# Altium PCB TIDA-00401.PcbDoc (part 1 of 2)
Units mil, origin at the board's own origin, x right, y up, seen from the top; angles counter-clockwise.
Board outline 3543.31 x 2362.2 mil, 2 copper layers (Top Layer, Bottom Layer), stack 62 mil thick; 132 components, 43 nets, 274 pads, 44 vias.
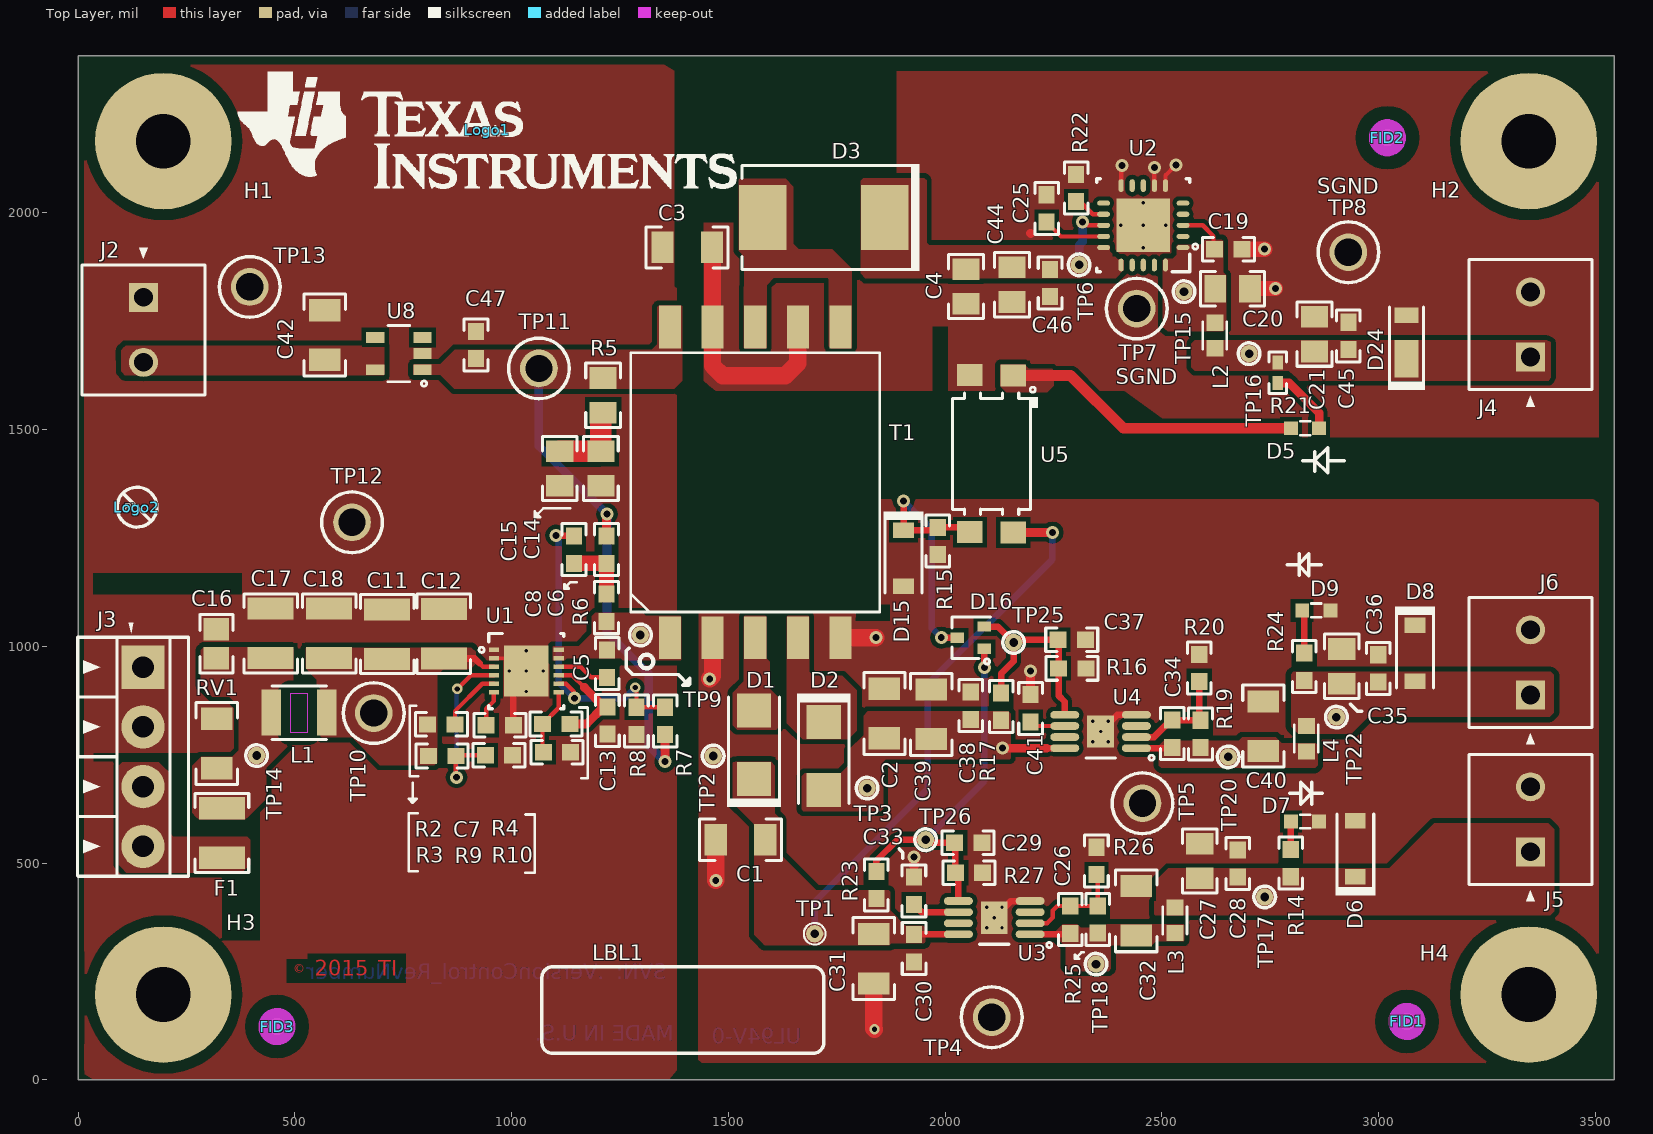
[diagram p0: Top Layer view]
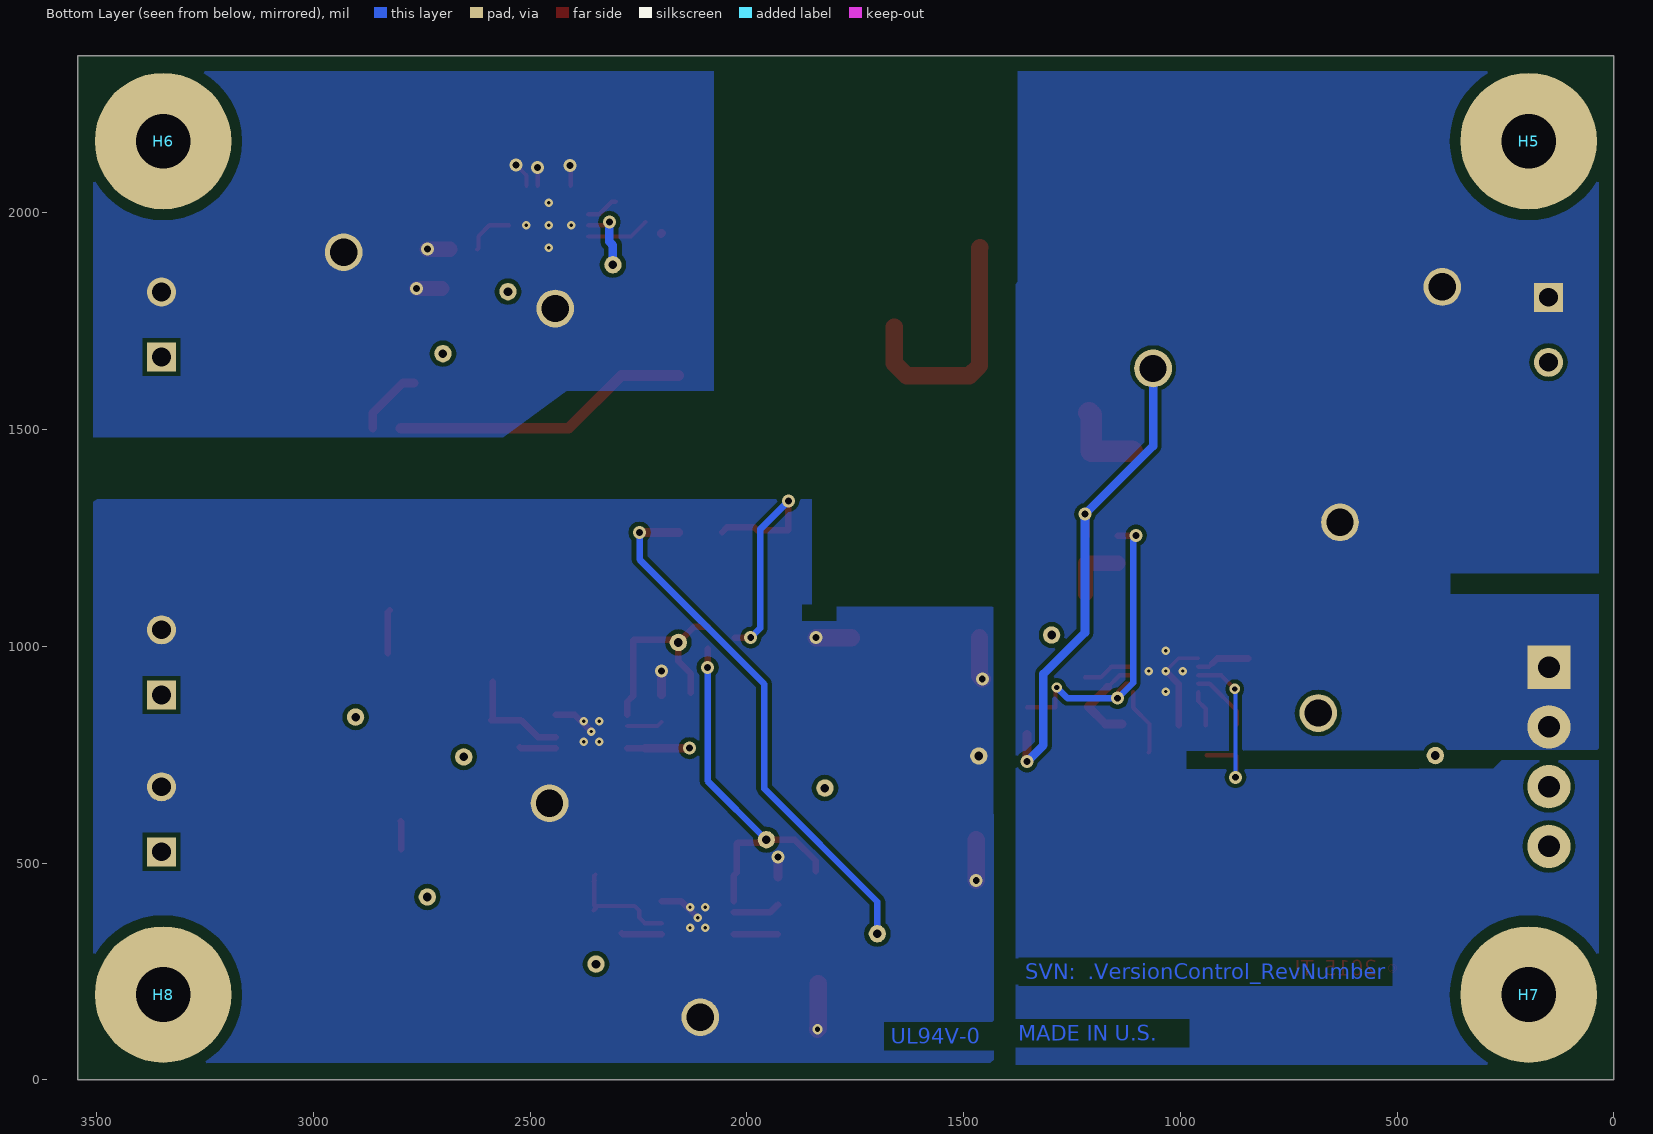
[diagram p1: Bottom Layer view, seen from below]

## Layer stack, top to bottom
Top Layer: signal copper 1.4
Dielectric: core 59.2, FR-4, Dk 4.8
Bottom Layer: signal copper 1.4

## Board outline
0,0 0,2362.2 3543.31,2362.2 3543.31,0

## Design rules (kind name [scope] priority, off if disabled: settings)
AcuteAngle [All] p1: minimum=4.50000000000000E+0001 checktracksonly=FALSE
AssemblyTestPointUsage [All] p1: valid=2
Clearance Clearance_mh [(InComponentClass('Mounting Holes')) vs InPolygon] p1: gap=25
Clearance "Clearance POLYGON TO POLYGON" [InPolygon vs InPolygon] p2: gap=12
Clearance Clearance_BoardEdge [OnCopper and Not InComponentClass('Logo') and not InComponentClass('FiducialMark') and not InRegion(1000,500,4000,800) and Not IsKeepout vs IsKeepOut] p3: gap=30
Clearance Clearance_Poly [InPolygon] p4: gap=10
Clearance "Clearance U3 AND U4" [(InPadClass('u3 and u4'))] p5: gap=7.87
Clearance "Clearance_same net" [IsPad vs IsVia] p6: gap=5
Clearance Clearance_1 [All] p7: gap=9
Clearance Clearance_BoardEdge_MountingHoles [OnCopper and InComponentClass('Mounting Holes') vs IsKeepOut] p8: gap=30
Clearance Clearance_BoardEdge_Poly [OnCopper and InPoly vs IsKeepOut] p9: gap=30
ComponentClearance ComponentClearance_Shunt [InComponentClass('Header') vs InComponentClass('Shunt')] p1 off: gap=0 collisioncheckmode=3 verticalgap=0 showdistances=FALSE
ComponentClearance ComponentClearance_MountingHoles_FiducialMarks [InComponentClass('Mounting Holes') vs InComponentClass('FiducialMark')] p2 off: gap=50 collisioncheckmode=3 verticalgap=10 showdistances=FALSE
ComponentClearance ComponentClearance_Logo [InComponentClass('Logo')] p3 off: gap=50 collisioncheckmode=3 verticalgap=10 showdistances=FALSE
ComponentClearance ComponentClearance_ScrewToNut [(HasFootprint('NY PMS 440 0025 PH')) vs (HasFootprint('Keystone_1902C'))] p4 off: gap=5 collisioncheckmode=3 verticalgap=10 showdistances=FALSE
ComponentClearance ComponentClearance_MountingHoles [InComponentClass('Mounting Holes')] p5 off: gap=50 collisioncheckmode=3 verticalgap=100000 showdistances=FALSE
ComponentClearance ComponentClearance_SmallPassives [HasFootprint('0201*') or HasFootprint('0402*') or HasFootprint('0508') or HasFootprint('0603*') or HasFootprint('0612') or HasFootprint('0805*') or HasFootprint('0815*') or HasFootprint('0830*') or HasFootprint('1206*') or HasFootprint('1210*') or HasFootprint('1808*') or HasFootprint('1812*') or HasFootprint('1825*') or HasFootprint('2010*') or HasFootprint('2220*') or HasFootprint('2225*') or HasFootprint('2512*') or HasFootprint('2728*') or HasFootprint('3518*') vs HasFootprint('0201*') or HasFootprint('0402*') or HasFootprint('0508') or HasFootprint('0603*') or HasFootprint('0612') or HasFootprint('0805*') or HasFootprint('0815*') or HasFootprint('0830*') or HasFootprint('1206*') or HasFootprint('1210*') or HasFootprint('1808*') or HasFootprint('1812*') or HasFootprint('1825*') or HasFootprint('2010*') or HasFootprint('2220*') or HasFootprint('2225*') or HasFootprint('2512*') or HasFootprint('2728*') or HasFootprint('3518*')] p6 off: gap=20 collisioncheckmode=3 verticalgap=10 showdistances=FALSE
ComponentClearance ComponentClearance_THtoSMT [IsThruComponent vs IsSMTComponent] p7 off: gap=35 collisioncheckmode=3 verticalgap=30 showdistances=FALSE
ComponentClearance ComponentClearance_THtoTH [IsThruComponent vs IsThruComponent] p8 off: gap=20 collisioncheckmode=3 verticalgap=5 showdistances=FALSE
ComponentClearance [All] p9 off: gap=20 collisioncheckmode=3 verticalgap=10 showdistances=FALSE
DiffPairsRouting [All] p1: maxlimit=100 minlimit=10 mostfreqgap=10 maxuncoupledlength=1000
FabricationTestPointUsage TestPointUsage [All] p1: valid=2 allowmultiple=FALSE
FabricationTestpoint Testpoint [All] p1: side=3 testpointundercomponent=TRUE minsize=40 maxsize=100 preferedsize=60 minholesize=0 maxholesize=40 preferedholesize=32 testpointgrid=1 allowsidetop=TRUE allowsidebottom=TRUE usegrid=TRUE gridtolerance=0.01
FanoutControl Fanout_LCC [IsLCC] p1: bgadir=Out bgaviamode=Centered fanoutstyle=Auto fanoutdirection=Alternating viagrid=1 // Fanout_LCC (Default Rule)
FanoutControl Fanout_BGA [IsBGA] p2: bgadir=Out bgaviamode=Centered fanoutstyle=Auto fanoutdirection=Alternating viagrid=1 // Fanout_BGA (Default Rule)
FanoutControl Fanout_Default [All] p4: bgadir=Out bgaviamode=Centered fanoutstyle=Auto fanoutdirection=Alternating viagrid=1 // Fanout_Default (Default Rule)
FanoutControl Fanout_Small [(CompPinCount < 5)] p5: bgadir=Out bgaviamode=Centered fanoutstyle=Auto fanoutdirection=OutThenIn viagrid=1 // Fanout_Small (Default Rule)
HoleSize [All] p1: absolutevalues=TRUE maxlimit=500 minlimit=7.8 maxpercent=80.000 minpercent=20.000
MinimumAnnularRing MinimumAnnularRing_ThermalPadVias [IsVia and InAnyComponent] p1: minimumring=5
MinimumAnnularRing [All] p2: minimumring=5
MinimumSolderMaskSliver MinimumSolderMaskSliver_Logo [InComponentClass('Logo') vs InComponentClass('Logo')] p1: minsoldermaskwidth=0.7
MinimumSolderMaskSliver [All] p2: minsoldermaskwidth=3.94
PlaneConnect [All] p1: planeconnectstyle=Direct reliefexpansion=10 reliefentries=4 reliefconductorwidth=10 reliefairgap=10
PolygonConnect [All] p1: connectstyle=Direct reliefconductorwidth=10 reliefentries=4 polygonreliefangle="90 Angle"
RoutingVias [All] p1: holewidth=10 width=20 viastyle="Through Hole" minholewidth=12 minwidth=24 maxholewidth=16 maxwidth=30
RoutingVias RoutingVias_1 [All] p2: holewidth=12 width=24 viastyle="Through Hole" minholewidth=7.87 minwidth=19.68 maxholewidth=16 maxwidth=30
RoutingVias ThermalPadVias [IsVia and InAnyComponent] p3: holewidth=7.87 width=19.68 viastyle="Through Hole" minholewidth=10 minwidth=20 maxholewidth=12.99 maxwidth=23.62
SMDToCorner [All] p1 off: distance=30000
SilkToSilkClearance SilkToSilkClearance_Pb-FreeLogo [(HasFootprint('Pb-Free_Overlay_Medium') OR HasFootprint('Pb-Free_Overlay_Small')) vs (HasFootprint('Pb-Free_Overlay_Medium') OR HasFootprint('Pb-Free_Overlay_Small'))] p1: silktosilkclearance=0
SilkToSilkClearance [All] p2: silktosilkclearance=5
SilkscreenOverComponentPads [IsPad] p1: minsilkscreentomaskgap=5
SolderMaskExpansion [All] p1: expansion=2.5
Width [All] p1: maxlimit=100 minlimit=6 preferedwidth=10 checkconnectedcopper=TRUE
14 further rules are at their usual default settings.

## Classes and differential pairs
component class TIDA-00401_LDO_1: C19 C20 C21 C25 C26 C27 C28 C29 C30 C31 C32 C33 C34 C35 C36 C37 C38 C39 C40 C41 C44 C45 C46 D5 D6 D7 D8 D9 D15 D16 D24 J4 J5 J6 L2 L3 L4 R14 R15 R16 R17 R19 R20 R21 R22 R23 R24 R25 R26 R27 TP15 TP16 TP17 TP18 TP20 TP22 TP25 TP26 U2 U3 U4 U5
component class "Mounting Holes": H1 H2 H3 H4
component class Logo: Logo1
component class TIDA-00401_HW_1: FID1 FID2 FID3 H1 H2 H3 H4 H5 H6 H7 H8 LBL1 Logo1 Logo2 ZZ1 ZZ2 ZZ3 ZZ4
component class FiducialMark: FID1 FID2 FID3
component class AssemblyNote: ZZ1 ZZ2 ZZ3 ZZ4
component class Label: LBL1
component class TIDA-00401_1: C1 C2 C3 C4 C5 C6 C7 C8 C11 C12 C13 C14 C15 C16 C17 C18 C42 C47 D1 D2 D3 F1 J2 J3 L1 R2 R3 R4 R5 R6 R7 R8 R9 R10 RV1 T1 TP1 TP2 TP3 TP4 TP5 TP6 TP7 TP8 TP9 TP10 TP11 TP12 TP13 TP14 U1 U8
pad class "u3 and u4": U3-1 U3-2 U3-3 U3-4 U3-5 U3-6 U3-7 U3-8 U3-9 U4-1 U4-2 U4-3 U4-4 U4-5 U4-6 U4-7 U4-8 U4-9

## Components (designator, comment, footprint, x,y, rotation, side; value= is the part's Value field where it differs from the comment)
C1 "GRM31CR71H475KA12L" 1206 1528,554 r0 top
C2 "GRM31CR71H475KA12L" 1206 1860,845 r270 top
C3 "VJ1206A102JXGAT5Z" 1206 1405,1920 r180 top
C4 "EMK212BJ106KG-T" 0805_HV 2048,1830 r270 top
C5 "C0603C104J3RAC" 0603#1 1220.2,959.91 r270 top
C6 "C0603C222K5RAC" 0603#1 1219,1223 r90 top
C7 "GRM188R71C223KA01D" 0603#1 972.8,817.84 r0 top
C8 "C0603C104J3RAC" 0603#1 1144,1223 r90 top
C11 "GRM32ER71H106KA12L" 1210 713,1028 r90 top
C12 "GRM32ER71H106KA12L" 1210 844,1029 r90 top
C13 "GRM188R71E105KA12D" 0603#1 1221,829 r270 top
C14 "EMK212BJ106KG-T" 0805_HV 1206,1410 r270 top
C15 "EMK212BJ106KG-T" 0805_HV 1111,1410 r270 top
C16 "C0805C104K1RACTU" 0805 319,1006 r90 top
C17 "GRM32ER71H106KA12L" 1210 444,1030 r90 top
C18 "GRM32ER71H106KA12L" 1210 579,1030 r90 top
C19 "06035C104KAT2A" 0603#1 2653,1916 r180 top
C20 "GRM21BR61C226ME44" 0805_HV 2663,1825 r0 top
C21 "C2012X5R1H475K125AB" 0805_HV 2852,1720 r90 top
C25 "C1608X7R1E105K080AB" 0603#1 2234,2010 r90 top
C26 "06031C103JAT2A" 0603#1 2288.32,369.52 r90 top
C27 "C2012X5R1H475K125AB" 0805_HV 2587,505 r270 top
C28 "06035C104KAT2A" 0603#1 2675,499 r270 top
C29 "06031C103JAT2A" 0603#1 2053,547 r0 top
C30 "06035C104KAT2A" 0603#1 1928.32,303.52 r90 top
C31 "GRM31CR71H475KA12L" 1206 1835.32,279.52 r270 top
C32 "GRM31CR71E106KA12L" 1206 2441,390 r90 top
C33 "06031C103JAT2A" 0603#1 1928,436 r90 top
C34 "06031C103JAT2A" 0603#1 2523.54,798.49 r90 top
C35 "C2012X5R1H475K125AB" 0805_HV 2915,954 r270 top
C36 "06035C104KAT2A" 0603#1 2999,949 r270 top
C37 "06031C103JAT2A" 0603#1 2292,1015 r0 top
C38 "06035C104KAT2A" 0603#1 2059,863 r270 top
C39 "GRM31CR71H475KA12L" 1206 1968,843 r90 top
C40 "GRM31CR71E106KA12L" 1206 2734,816 r90 top
C41 "06031C103JAT2A" 0603#1 2197,857 r90 top
C42 "GRM31CR71H475KA12L" 1206 569,1718 r270 top
C44 "GRM21BR61C226ME44" 0805_HV 2154,1834 r270 top
C45 "06035C104KAT2A" 0603#1 2930,1716 r270 top
C46 "06035C104KAT2A" 0603#1 2242,1838 r90 top
C47 "EMK107B7105KA-T" 0603#1 918,1695 r90 top
D1 "B160-13-F" SMA 1559,773 r90 top
D2 "B160-13-F" SMA 1720,747 r270 top
D3 "B350-13-F" SMC 1720,1989 r180 top
D5 "LED_LG L29K-G2J1-24-Z" LED0603AA 2830,1503 r0 top
D6 "DZ2W18000L" SOD-123 2946,533 r90 top
D7 "LED_LG L29K-G2J1-24-Z" LED0603AA 2830,596 r180 top
D8 "DZ2W18000L" SOD-123 3084,984 r270 top
D9 "LED_LG L29K-G2J1-24-Z" LED0603AA 2856,1083 r0 top
D15 "BZT52C5V1-G3-08" SOD-123 1904,1203 r270 top
D16 "BAT54AWT-TP" SOT-323 2059,1020 r180 top
D24 "PTZTE255.6B" powerDI123 3064,1713 r90 top
F1 "0ZCB0020FF2E" 1210 332,569.24 r270 top
FID1 "Fiducial" Fiducial10-20 3065,134.85 r0 top
FID2 "Fiducial" Fiducial10-20 3020,2173 r0 top
FID3 "Fiducial" Fiducial10-20 459,123 r0 top
H1 "NY PMS 440 0025 PH" "NY PMS 440 0025 PH" 196.85,2165.35 r0 top locked
H2 "NY PMS 440 0025 PH" "NY PMS 440 0025 PH" 3346.46,2165.35 r0 top
H3 "NY PMS 440 0025 PH" "NY PMS 440 0025 PH" 196.85,196.85 r0 top locked
H4 "NY PMS 440 0025 PH" "NY PMS 440 0025 PH" 3346.46,196.85 r0 top locked
H5 "1902C" Keystone_1902C 196.85,2165.35 r180 bottom locked
H6 "1902C" Keystone_1902C 3346.46,2165.35 r180 bottom
H7 "1902C" Keystone_1902C 196.85,196.85 r180 bottom locked
H8 "1902C" Keystone_1902C 3346.46,196.85 r180 bottom locked
J2 "Vout Primary" PhoenixConact_1727010 151,1730 r270 top
J3 "ED555/4DS" TERM_BLK_ED555-4DS 150,952 r270 top
J4 "+5V" PhoenixConact_1727010 3350,1742 r90 top
J5 "+15V" PhoenixConact_1727010 3350,601 r90 top
J6 "-15V" PhoenixConact_1727010 3350,963 r90 top
L1 "3.3µH" IND_B82422H 510,847 r0 top
L2 "1000 OHM" FB0603 2622,1717 r270 top
L3 "1000 OHM" FB0603 2530,368 r90 top
L4 "1000 OHM" FB0603 2833,787 r90 top
LBL1 "Size: 0.65\" x 0.20 \"" Label_650x200 1395,161 r180 top
Logo1 "Texas Instruments" TI_Stacked_Overlay_Medium 944,2191 r0 top
Logo2 "Pb-Free Symbol" Pb-Free_Overlay_Small 136,1321 r0 top
R2 "CRCW0603487KFKEA" 0603#1 838,820 r180 top
R3 "CRCW0603100KFKEA" 0603#1 840,747 r180 top
R4 "CRCW06030000Z0EA" 0603#1 1102.8,820.84 r180 top
R5 "CRCW08050000Z0EA" 0805_HV 1211,1579 r90 top
R6 "CRCW0603100KFKEA" 0603#1 1219,1089 r90 top
R7 "CRCW060310K0FKEA" 0603#1 1354,828 r270 top
R8 "CRCW06031K82FKEA" 0603#1 1288,828 r90 top
R9 "CRCW060318K2FKEA" 0603#2 971,749 r180 top
R10 "CRCW06030000Z0EA" 0603#1 1104.8,755.84 r180 top
R14 "CRCW06034K70JNEA" 0603#1 2797,500 r90 top
R15 "CRCW06034K70JNEA" 0603#1 1983,1243 r270 top
R16 "CRCW06032K20JNEA" 0603#1 2293,949 r180 top
R17 "CRCW06030000Z0EA" 0603#1 2129,861 r270 top
R19 "CRCW0402110KFKED" 0603#1 2589,798 r90 top
R20 "TNPW04029K42BEED" 0603#1 2586,950 r90 top
R21 "CRCW04021K20JNED" 0402 2767,1631 r270 top
R22 "CRCW06030000Z0EA" 0603#1 2302,2057 r90 top
R23 "CRCW06030000Z0EA" 0603#1 1841.32,449.52 r270 top
R24 "CRCW06034K70JNEA" 0603#1 2828,953 r90 top
R25 "CRCW0402110KFKED" 0603#1 2352,370 r90 top
R26 "TNPW04029K42BEED" 0603#1 2349,505 r90 top
R27 "CRCW06032K20JNEA" 0603#1 2055,478 r180 top
RV1 "VC080530A650DP" 1206 320,776 r270 top
T1 "750342706" TR_750342706 1365,1020 r90 top
TP1 "TP1_PD40_D0.5_S50" TP1_PD40_D0.5_S50 1699,337 r90 top
TP2 "TP1_PD40_D0.5_S50" TP1_PD40_D0.5_S50 1465,747 r0 top
TP3 "TP1_PD40_D0.5_S50" TP1_PD40_D0.5_S50 1820,673 r0 top
TP4 "15GND" Keystone5011 2107.32,144.52 r0 top
TP5 "15GND" Keystone5011 2455,638 r0 top
TP6 "TP1_PD40_D0.5_S50" TP1_PD40_D0.5_S50 2309,1880 r0 top
TP7 "SGND" Keystone5011 2442,1779 r0 top
TP8 "SGND" Keystone5011 2930,1909 r0 top
TP9 "TP1_PD40_D0.5_S50" TP1_PD40_D0.5_S50 1297,1026 r0 top
TP10 "+Vin" Keystone5010 682,846 r0 top
TP11 "9V_Non_ISO" Keystone5011 1063,1641 r0 top
TP12 "GNDin" Keystone5011 632,1286 r0 top
TP13 "PGND" Keystone5127 396,1829 r0 top
TP14 "TP1_PD40_D0.5_S50" TP1_PD40_D0.5_S50 412,748 r90 top
TP15 "TP1_PD40_D0.5_S50" TP1_PD40_D0.5_S50 2551,1818 r90 top
TP16 "TP-038" TP1_PD40_D0.5_S50 2701,1675 r90 top
TP17 "TP-038" TP1_PD40_D0.5_S50 2737,422 r90 top
TP18 "TP1_PD40_D0.5_S50" TP1_PD40_D0.5_S50 2348,267 r90 top
TP20 "TP1_PD40_D0.5_S50" TP1_PD40_D0.5_S50 2653,745 r90 top
TP22 "TP-038" TP1_PD40_D0.5_S50 2902.33,836.72 r90 top
TP25 "TP1_PD40_D0.5_S50" TP1_PD40_D0.5_S50 2158,1009 r90 top
TP26 "TP1_PD40_D0.5_S50" TP1_PD40_D0.5_S50 1955,554 r90 top
U1 "LM5160DNT" DNT0012B 1034,943 r0 top
U2 "TPS7A4700RGW" RGW0020A 2457,1971 r180 top
U3 "TPS7A4901DGNR" DGN0008D_N 2113.32,374.2 r180 top
U4 "TPS7A3001DGNR" DGN0008D_N 2358.54,803.49 r180 top
U5 "FOD817DS" N04C 2107,1444 r270 top
U8 "TPS709XXDBV" DBV-5 740,1675 r180 top
ZZ1 "This Assembly Note is for PCB labels only" AssemblyNoteLabel 311,2930 r0 top
ZZ2 "These assemblies are ESD sensitive, ESD precautions shall be observed." AssemblyNote 310,2859.11 r0 top
ZZ3 "These assemblies must be clean and free from flux and all contaminants. Use of no clean flux is not acceptable." AssemblyNote 310,2785.56 r0 top
ZZ4 "These assemblies must comply with workmanship standards IPC-A-610 Class 2, unless otherwise specified." AssemblyNote 312,2705 r0 top

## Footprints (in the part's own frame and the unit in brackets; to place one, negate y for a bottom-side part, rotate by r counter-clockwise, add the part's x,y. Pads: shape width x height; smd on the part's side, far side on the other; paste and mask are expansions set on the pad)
0402 [mm] "0402 from SM-752 data"
  rect 0.8x0.6 smd: 1(-0.6,0) 2(0.6,0)
  silkscreen extent -1.22,-0.52 1.22,0.52, body extent -0.55,-0.3 0.55,0.3, height 0.6
0603#1 [mm] "0603 from SM-752 data"
  rect 1x0.95 smd: 1(-0.8,0) 2(0.8,0)
  silkscreen extent -1.52,-0.69 1.52,0.69, body extent -0.87,-0.47 0.87,0.47, height 0.85
0603#2 [mm] "0603 from SM-752 data"
  rect 1x0.95 smd: 1(-0.8,0)
  rect 1x0.95 smd mask+0.064: 2(0.8,0)
  silkscreen extent -1.52,-0.69 1.52,0.69, body extent -0.87,-0.47 0.87,0.47, height 0.85
0805 [mm] "0805 from SM-752 data"
  rect 1.3x1.5 smd: 1(-0.85,0) 2(0.85,0)
  silkscreen extent -1.72,-0.97 1.72,0.97, body extent -1.1,-0.72 1.1,0.72, height 1.1
0805_HV [mil] "0805 with 30mil clearance between pads"
  rect 50x63 smd: 1(-40,0) 2(40,0)
  silkscreen extent -74,-40 74,40, body extent -43,-29 43,29, height 43
1206 [mm] "1206 from SM-752 data"
  rect 1.3x1.85 smd: 1(-1.45,0) 2(1.45,0)
  silkscreen extent -2.4,-1.21 2.4,1.21, body extent -1.7,-0.9 1.7,0.9, height 1.35
1210 [mm] "1210 from SM-752 data"
  rect 1.3x2.7 smd: 1(-1.45,0) 2(1.45,0)
  silkscreen extent -2.32,-1.57 2.32,1.57, body extent -1.7,-1.35 1.7,1.35, height 1.35
AssemblyNote [mil] "Assembly Note"
AssemblyNoteLabel [mil] "Assembly Note for PCB Labels"
DBV-5 [mil]
  rect 42x25 smd: 1(-54.5,37) 2(-54.5,0) 3(-54.5,-37) 4(54.5,-37) 5(54.5,37)
  silkscreen extent -64,-65 25,75
DGN0008D_N [mm] "TSOP, 8-Leads, Body 3x3mm, Pitch 0.65mm, Thermal Pad 1.89x1.57mm, IPC Medium Density"
  oval 1.7x0.45 smd mask+0.048: 1(-2.1,0.975) 2(-2.1,0.325) 3(-2.1,-0.325) 4(-2.1,-0.975) 5(2.1,-0.975) 6(2.1,-0.325) 7(2.1,0.325) 8(2.1,0.975)
  rect 1.57x1.89 smd mask+0.076: 9(0,0)
  silkscreen extent -0.85,1.55 0.85,1.55, body extent -2.45,-1.5 2.45,1.5, height 0.94
DNT0012B [mm] "SON, 12-Leads, Body 4x4mm, Pitch 0.5mm"
  rect 0.6x0.25 smd: 1(-1.9,1.25) 2(-1.9,0.75) 3(-1.9,0.25) 4(-1.9,-0.25) 5(-1.9,-0.75) 6(-1.9,-1.25) 7(1.9,-1.25) 8(1.9,-0.75) 9(1.9,-0.25) 10(1.9,0.25) 11(1.9,0.75) 12(1.9,1.25)
  rect 2.6x3 smd paste-1.3: 13(0,0)
  silkscreen extent -2.2,-2.2 2.2,2.2, body extent -2.05,-2.05 2.05,2.05, height 0.81
FB0603 [mm]
  rect 0.95x1 smd: 1(-0.75,0) 2(0.75,0)
  silkscreen extent -0.8,-0.7 0.8,0.7
Fiducial10-20 [mm]
  round 1 smd mask+0.5: 1(0,0)
  Top Layer keep-out circle w1.178: c0,0 r0.5
IND_B82422H [mm]
  rect 1.15x2.7 smd: 1(-1.625,0) 2(1.625,0)
  Top Layer keep-out region: -0.507,-1.147 0.509,-1.147 0.509,1.119 -0.507,1.119
  silkscreen extent -1.6,-1.57 1.6,1.57, body extent -1.6,-1.25 1.6,1.25, height 2.4
Keystone5010 [mil] "Keystone Multipurpose loops"
  round 87 hole 63: 1(0,0)
  silkscreen extent -70,-70 70,70, body extent -63,-63 63,62, height 319
Keystone5011 [mil] "Keystone Multipurpose loops"
  round 87 hole 63: 1(0,0)
  silkscreen extent -70,-70 70,70, body extent -63,-63 63,62, height 319
Keystone5127 [mil] "Keystone Multipurpose loops"
  round 87 hole 63: 1(0,0)
  silkscreen extent -70,-70 70,70, body extent -63,-63 63,62, height 319
Keystone_1902C [mil] "Hex Standoff, 4-40 threaded, nylon"
  body extent -145,-126 146,126, height 501
Label_650x200 [mil] "Thermal Transfer Label"
  round 1 on Mech13: 0(0,0)
  silkscreen extent -325,-100 325,100, body extent -326,-101 326,101, height 1
LED0603AA [mil]
  rect 32x32 smd: 1(-32.48,0) 2(32.48,0)
  silkscreen extent -11,-16 11,16
N04C [mm] "FAIRCHILD"
  rect 1.3x1.5 smd mask+0.065: 1(-4.587,1.27) 2(-4.612,-1.27) 3(4.588,-1.27) 4(4.613,1.27)
  silkscreen extent -3.91,-2.3 3.56,2.72, body extent -5.08,-2.3 5.08,2.3, height 3.87
"NY PMS 440 0025 PH" [mm] "4-40 nylon screw and mounting hole"
  round 8 hole 3.2: 1(0,0)
  body extent -3.3,-3.3 3.3,3.3, height 2.69
Pb-Free_Overlay_Small [mil]
  silkscreen extent -46,-46 46,46
PhoenixConact_1727010 [mm]
  rect 1.7x1.7 hole 1.1: 1(-1.905,0)
  round 1.7 hole 1.1: 2(1.905,0)
  silkscreen extent -4.8,-3.6 3.81,3.6, body extent -3.81,-3.6 3.81,3.7, height 8.52
powerDI123 [mm] "Diodes Inc recommended land pattern, document number DS30628 Rev. 6-2"
  rect 2.2x1.4 smd: 1(-1.275,0)
  rect 0.9x1.4 smd: 2(1.275,0)
  silkscreen extent -3.1,-1.09 1.76,1.09, body extent -2.38,-0.97 1.52,0.96, height 1
RGW0020A [mm] "QFN, 20-Leads, Body 5x5mm, Pitch 0.65mm, Thermal Pad 3.15x3.15mm, TI Recommended"
  oval 0.75x0.3 smd: 1(-2.325,1.3) 2(-2.325,0.65) 3(-2.325,0) 4(-2.325,-0.65) 5(-2.325,-1.3) 11(2.325,-1.3) 12(2.325,-0.65) 13(2.325,0) 14(2.325,0.65) 15(2.325,1.3)
  oval 0.3x0.75 smd: 6(-1.3,-2.325) 7(-0.65,-2.325) 8(0,-2.325) 9(0.65,-2.325) 10(1.3,-2.325) 16(1.3,2.325) 17(0.65,2.325) 18(0,2.325) 19(-0.65,2.325) 20(-1.3,2.325)
  rect 3.15x3.15 smd paste-1.575: 21(0,0)
  silkscreen extent -2.73,-2.73 2.73,2.73, body extent -2.58,-2.57 2.57,2.58, height 1.01
SMA [mm] "Molded Diode, 2-Leads, Body 4.3x2.6mm, IPC Medium Density, based on OnSemi component dimensions and land pattern"
  rect 2x2 smd: 1(-2,0) 2(2,0)
  silkscreen extent -3.66,-1.57 2.79,1.57, body extent -2.6,-1.3 2.6,1.3, height 2.42
SMC [mil] "Molded Diode, 2-Leads, Body 6.9x5.8mm, IPC Medium Density, based on OnSemi component dimensions and land patterns"
  rect 110x150 smd: 1(-140.49,0) 2(140.49,0)
  silkscreen extent -221,-124 189,123, body extent -156,-116 156,116, height 91
SOD-123 [mm] "On Semi recommended land pattern"
  rect 0.915x1.22 smd: 1(-1.637,0) 2(1.637,0)
  silkscreen extent -2.74,-1.17 2.03,1.17, body extent -1.93,-0.9 1.93,0.9, height 1.35
SOT-323 [mm] "Zetex recommended land pattern.  March 2007"
  rect 0.8x0.6 smd: 1(-0.8,0.65) 2(-0.8,-0.65) 3(0.8,0)
  silkscreen extent -1.14,-1.22 1.09,1.55, body extent -1.13,-1.13 1.12,1.12, height 1.13
TERM_BLK_ED555-4DS [mm]
  rect 2.54x2.54 hole 1.27: 1(0,0)
  round 2.54 hole 1.27: 2(3.5,0) 3(7,0) 4(10.5,0)
  silkscreen extent -2.59,-3.83 12.25,2.67, body extent -1.75,-3.8 12.25,2.7, height 8.2
TI_Stacked_Overlay_Medium [mil]
  silkscreen extent -576,-136 576,134
TP1_PD40_D0.5_S50 [mil]
  round 40 hole 20: 1(0,0)
  silkscreen extent -25,-25 25,25
TR_750342706 [mm] "Transformer WE_750342706"
  rect 2.5x1.3 smd: 1(0,0) 2(0,-2.5) 3(0,-5) 4(0,-7.5) 5(0,-10) 6(18.2,-10) 7(18.2,-7.5) 8(18.2,-5) 9(18.2,-2.5) 10(18.2,0)
  silkscreen extent -1.8,-12.3 16.7,2.3, body extent -0.9,-12.3 19.1,2.3, height 8.25

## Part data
C1 C2 C31 C39 C42: "CAP, CERM, 4.7uF, 50V, +/-10%, X7R, 1206"
C3: "CAP, CERM, 1000pF, 1000V, +/-5%, C0G/NP0, 1206"
C4 C14 C15: "CAP, CERM, 10uF, 16V, +/-10%, X5R, 0805"
C5 C8: "CAP, CERM, 0.1uF, 25V, +/-5%, X7R, 0603"
C6: "CAP, CERM, 2200pF, 50V, +/-10%, X7R, 0603"
C7: "CAP, CERM, 0.022uF, 16V, +/-10%, X7R, 0603"
C11 C12 C17 C18: "CAP, CERM, 10uF, 50V, +/-10%, X7R, 1210"
C13 C25: "CAP, CERM, 1uF, 25V, +/-10%, X7R, 0603"
C16: "CAP, CERM, 0.1uF, 100V, +/-10%, X7R, 0805"
C19 C28 C30 C36 C38 C45 C46: "CAP, CERM, 0.1uF, 50V, +/-10%, X7R, 0603"
C20 C44: "CAP, CERM, 22uF, 16V, +/-20%, X5R, 0805"
C21 C27 C35: "CAP, CERM, 4.7uF, 50V, +/-10%, X5R, 0805"
C26 C29 C33 C34 C37 C41: "CAP, CERM, 0.01uF, 100V, +/-5%, X7R, 0603"
C32 C40: "CAP, CERM, 10uF, 25V, +/-10%, X7R, 1206"
C47: "CAP, CERM, 1 µF, 16 V, +/- 10%, X7R, 0603"
D1 D2: "Diode, Schottky, 60 V, 1 A, SMA"
D3: "Diode, Schottky, 50 V, 3 A, SMC"
D5 D7 D9: "LED SmartLED Green 570NM"
D6 D8: "Diode, Zener, 18V, 1W, SOD-123"
D15: "Diode, Zener, 5.1 V, 500 mW, SOD-123"
D16: "Diode, Schottky, 30 V, 0.2 A, SOT-323"
D24: "DIODE ZENER 5.9V 1W PMDS"
F1: library part 37215000001, "PTC RESTTBLE 0.05A 60V CHIP 1210"
FID1 FID2 FID3: "Fiducial mark.  There is nothing to buy or mount."
H1 H2 H3 H4: "Machine Screw, Round, #4-40 x 1/4, Nylon, Philips panhead"
H5 H6 H7 H8: "Standoff, Hex, 0.5\"L #4-40 Nylon"
J2 J4 J5 J6: library part 1727010, "Conn Term Block, 2POS, 3.81mm, TH"
J3: "Terminal Block, 6A, 3.5mm Pitch, 4-Pos, TH"
L1: library part IND_ELJEA_SERIES, "Inductor, Chip, ±10%"
L2: library part MMZ1608B102C, "FERRITE CHIP 1000 OHM 1500MA 0805"
L3 L4: library part MMZ1608B102C, "FERRITE CHIP 1000 OHM 300MA 0603"
LBL1: library part THT-14-423-10, "Thermal Transfer Printable Labels, 0.650\" W x 0.200\" H - 10,000 per roll"
Logo1: library part TI_Logo, "Texas Instrument Corporate Signature"
Logo2: library part Pb-Free
R2: "RES, 487k ohm, 1%, 0.1W, 0603"
R3: "RES, 100 k, 1%, 0.1 W, 0603"
R4 R10 R17 R22 R23: "RES, 0, 5%, 0.1 W, 0603"
R5: "RES, 0, 5%, 0.125 W, 0805"
R6: "RES, 100k ohm, 1%, 0.1W, 0603"
R7: "RES, 10.0k ohm, 1%, 0.1W, 0603"
R8: "RES, 1.82 k, 1%, 0.1 W, 0603"
R9: "RES, 18.2k ohm, 1%, 0.1W, 0603"
R14 R15 R24: "RES, 4.7k ohm, 5%, 0.1W, 0603"
R16 R27: "RES, 2.2 k, 5%, 0.1 W, 0603"
R19 R25: "RES, 110k ohm, 1%, 0.063W, 0402"
R20 R26: library part CRCW04029K31FKED, "RES, 9.42k ohm, 1%, 0.063W, 0402"
R21: "RES, 1.2k ohm, 5%, 0.063W, 0402"
RV1: library part VC120648D101DP, "VARISTOR 36.9V 30A 0805"
T1: library part 750342178, "Transformer, 50 uH, SMT"
TP1 TP2 TP3 TP6 TP9 TP14 TP15 TP18 TP20 TP25 TP26: library part TP-040_RND, "Test Point 40mil pad 20mil drill"
TP4 TP5 TP7 TP8 TP11 TP12: library part 5011, "Test Point, Multipurpose, Black, TH"
TP10: library part 5010, "Test Point, Multipurpose, Red, TH"
TP13: library part 5127, "Test Point, Multipurpose, Blue, TH"
TP16 TP17 TP22: "Test Point 40mil pad 20mil drill"
U1: "Wide Input 65V, 1.5A Synchronous Step-Down DC-DC Converter, DNT0012B"
U2: "36-V, 1-A, 4.17-µVRMS, RF LDO Voltage Regulator, RGW0020A"
U3: "Single Output High PSRR LDO, 150 mA, Adjustable 1.2 to 33 V Output, 3 to 36 V Input, with Ultra-Low Noise, 8-pin MSOP (DGN), -40 to 125 degC, Green (RoHS & no Sb/Br)"
U4: "Single Output High PSRR LDO, 200 mA, Adjustable -1.18 to -33 V Output, -3 to -36 V Input, with Ultra-Low Noise, 8-pin MSOP (DGN), -40 to 125 degC, Green (RoHS & no Sb/Br)"
U5: "Optocoupler, 5kV RMS, SMT"
U8: "IC,150mA, Ultra Low IQ, 1uA LDO Regulator with Enable"
ZZ1: library part AssemblyNoteLabel
ZZ2 ZZ3 ZZ4: library part AssemblyNote

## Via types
v1: diameter 30, hole 16, Top Layer to Bottom Layer, tented both sides, 21 vias
v2: diameter 19.68, hole 7.87, Top Layer to Bottom Layer, tented both sides, 20 vias
v3: diameter 24, hole 12, Top Layer to Bottom Layer, tented both sides, 3 vias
